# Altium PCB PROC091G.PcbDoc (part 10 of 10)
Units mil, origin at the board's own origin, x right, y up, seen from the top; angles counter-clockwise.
Board outline 4538.11 x 994.94 mil, 8 copper layers (Top Layer, GND1, Sig1, PWR1, PWR2, Sig2, GND2, Bottom Layer), stack 59.155 mil thick; 446 components, 329 nets, 5050 pads, 868 vias.
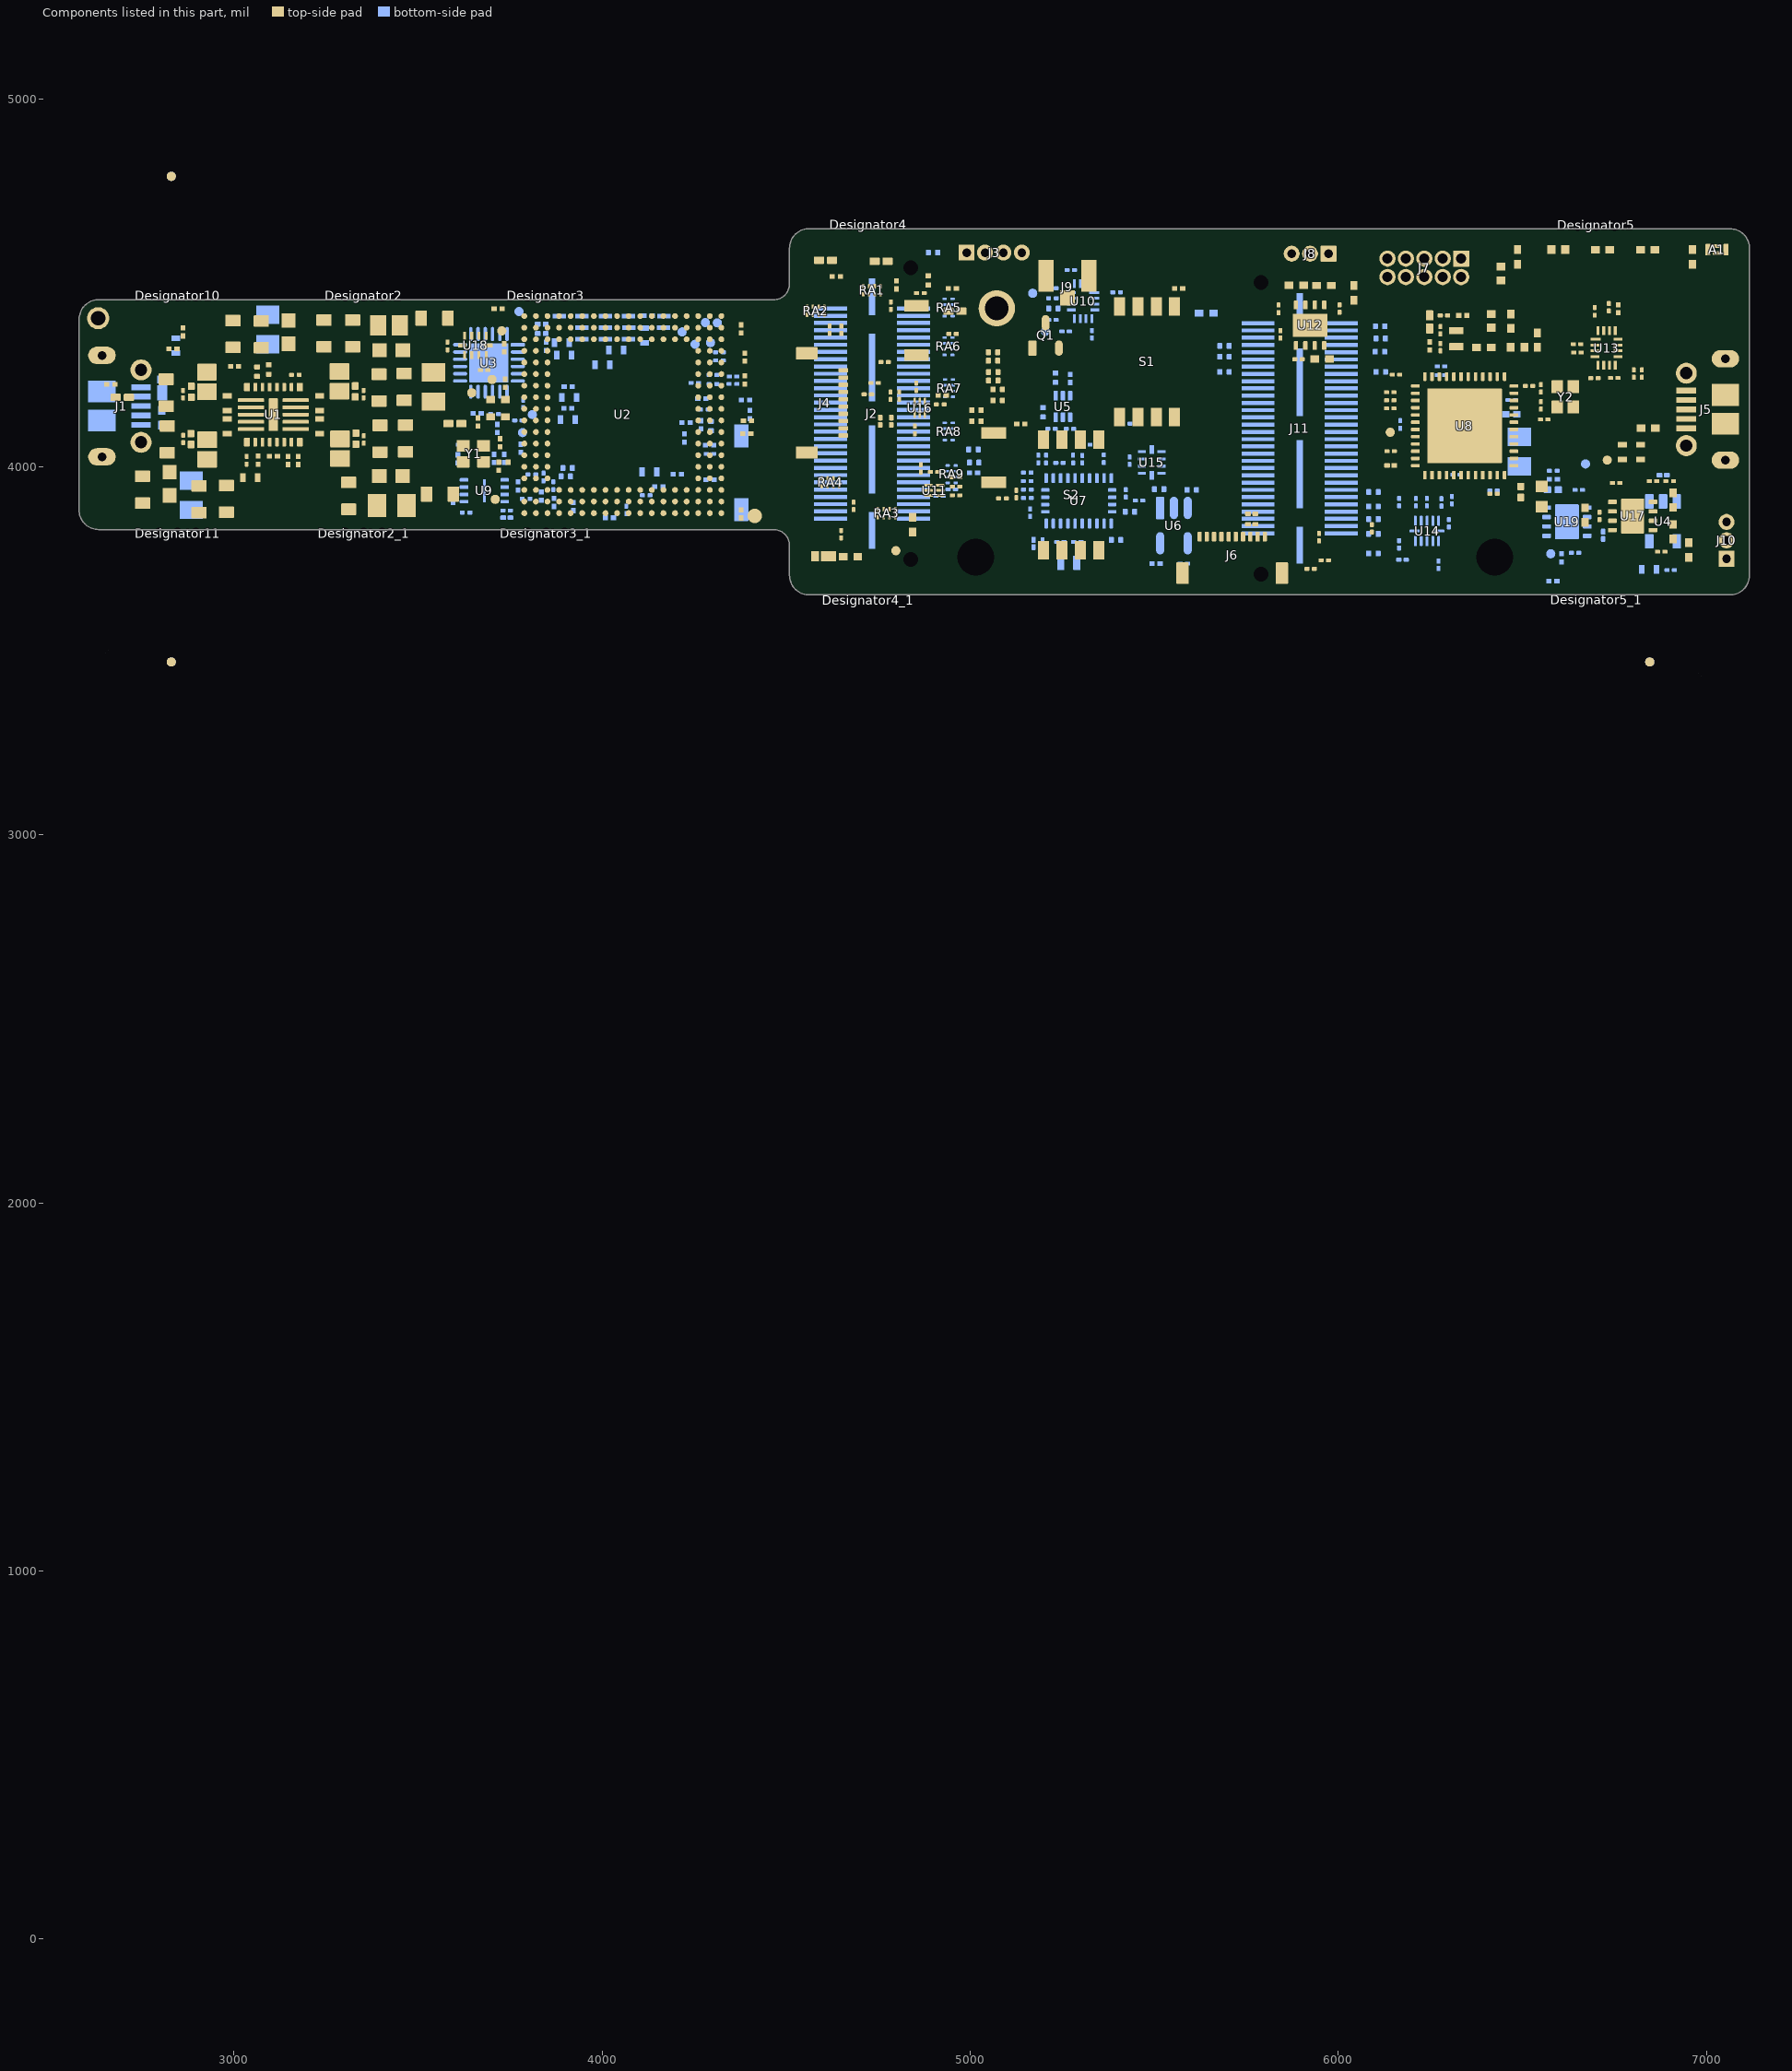
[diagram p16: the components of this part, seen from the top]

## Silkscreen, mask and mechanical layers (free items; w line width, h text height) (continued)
Mechanical 24:
  drawing of 10999 lines, arcs and shapes, not listed
  text "TP33" at 6097.58,6677.7 h30
  text "5V_LED" at 6651.08,6662.7 h30
  text "GND" at 6113.08,6617.7 h30
  text "32" at 8052.58,6517.7 h20
  text "17" at 8422.58,6517.7 h20
  text "U3" at 7956.58,6497.7 h30
  text "D1" at 6081.58,6467.7 h30
  text "33" at 7982.58,6452.7 h20
  text "16" at 8467.58,6452.7 h20
  text "SPARE" at 5513.58,6424.7 h30 r90
  text "DATA_TRAN_PRG" at 5228.58,6398.7 h30 r90
  text "SD_FULL" at 5443.58,6385.7 h30 r90
  text "HDR_ERR" at 5868.58,6380.7 h30 r90
  text "DDR_FULL" at 5588.58,6368.7 h30 r90
  text "LVDS_PATH_ERR" at 5798.58,6363.7 h30 r90
  text "FPGA_ERR" at 5658.58,6358.7 h30 r90
  text "D4" at 7528.58,6350.7 h30 r90
  text "D3" at 7023.58,6346.7 h30 r90
  text "EEPROM_RD_FAIL" at 5998.58,6341.7 h30 r90
  text "D2" at 6548.58,6341.7 h30 r90
  text "SD_DETECT" at 5368.58,6336.7 h30 r90
  text "SW1" at 5689.58,6332.7 h30
  text "6" at 5726.08,6292.7 h20
  text "12BIT_OFF" at 5764.08,6257.7 h30
  text "12BIT_ON" at 5209.58,6232.7 h30
  text "9" at 7141.08,6217.7 h20
  text "9" at 6171.08,6212.7 h20
  text "D6" at 6991.58,6212.7 h30
  text "D8" at 7491.58,6212.7 h30
  text "14BIT_OFF" at 5764.08,6207.7 h30
  text "D7" at 6516.58,6207.7 h30
  text "16" at 7372.58,6202.7 h20
  text "14BIT_ON" at 5209.58,6182.7 h30
  text "16" at 6372.58,6182.7 h20
  text "U1" at 6261.58,6162.7 h30
  text "U2" at 7231.58,6162.7 h30
  text "D5" at 6111.58,6147.7 h30
  text "16BIT_ON" at 5209.58,6132.7 h30
  text "48" at 7952.58,6117.7 h20
  text "3" at 5401.08,6097.7 h20
  text "16BIT_OFF" at 5717.58,6087.7 h30
  text "2" at 8776.08,6074.36 h25
  text "64" at 8412.58,6032.7 h20
  text "49" at 8027.58,6027.7 h20
  text "RADAR_FTDI" at 8900.08,6012.7 h30
  text "Y1" at 8771.58,6002.7 h30
  text "L1" at 5883.58,5997.7 h30
  text "L4" at 7673.58,5980.7 h30 r90
  text "L2" at 6693.58,5972.7 h30 r90
  text "L3" at 6888.58,5970.7 h30 r90
  text "8" at 8763.58,5905.2 h20 r90
  text "USER_SW3" at 5358.58,5867.2 h30 r90
  text "USER_SW2" at 5418.58,5867.2 h30 r90
  text "LVDS_CAPT" at 5743.58,5866.2 h30 r90
  text "USER_SW1" at 5473.58,5862.2 h30 r90
  text "HW_CONFIG" at 5520.25,5858.2 h30 r90
  text "RAW_MODE" at 5578.58,5857.2 h30 r90
  text "3" at 8856.08,5852.7 h20
  text "SD_STORE" at 5678.58,5852.2 h30 r90
  text "1243_MODE" at 5628.58,5843.2 h30 r90
  text "8" at 5296.08,5822.7 h20
  text "D9" at 8779.58,5802.7 h30
  text "LVDS_MODE_SEL" at 5238.58,5747.2 h30 r90
  text "4" at 8480.59,5723.37 h20
  text "5" at 8736.08,5697.7 h20
  text "Y2" at 8273.58,5675.7 h30 r90
  text "U4" at 8581.58,5652.7 h30
  text "2V5" at 7516.08,5622.2 h30 r90
  text "17" at 7892.58,5617.7 h20
  text "SW2" at 5828.58,5603.7 h30 r90
  text "32" at 7562.58,5587.7 h20
  text "U5" at 7176.58,5577.7 h30
  text "J1" at 9096.58,5577.7 h30
  text "5" at 7271.08,5552.7 h20
  text "8" at 7106.08,5547.7 h20
  text "33" at 7482.58,5522.7 h20
  text "16" at 7992.58,5507.7 h20
  text "1V35" at 6414.84,5503.2 h30 r90
  text "9" at 5311.08,5482.7 h20
  text "16" at 5752.58,5472.7 h20
  text "VCC_CORE" at 6179.84,5427.2 h30 r90
  text "U7" at 6421.58,5317.7 h30
  text "8" at 6541.08,5302.7 h20
  text "DATA_MODE" at 5673.58,5183.2 h30 r90
  text "SW_CONFIG" at 5618.58,5178.2 h30 r90
  text "48" at 7487.58,5157.7 h20
  text "ETH_STREAM" at 5773.58,5152.2 h30 r90
  text "AR1642_MODE" at 5723.58,5132.2 h30 r90
  text "DMM_PLAYBACK" at 5823.58,5111.2 h30 r90
  text "4" at 6291.08,5111.03 h20
  text "3" at 5316.08,5087.7 h20
  text "1V1" at 7156.08,5082.2 h30 r90
  text "5" at 6536.08,5072.7 h20
  text "49" at 7587.58,5062.68 h20
  text "64" at 7907.58,5062.68 h20
  text "U6" at 7736.58,5052.7 h30
  text "U8" at 6536.58,4977.7 h30
  text "3" at 6486.08,4937.7 h20
  text "6" at 6676.08,4837.7 h20
  text "4" at 6491.08,4827.7 h20
  text "RADAR_5V_IN" at 5223.58,4770.2 h30 r90
  text "DC_JACK_5V_IN" at 5868.58,4762.2 h30 r90
  text "SW3" at 5449.58,4742.7 h30
  text "U10" at 7609.58,4727.7 h30
  text "U11" at 8089.58,4727.7 h30
  text "FPGA_PROGRAMN_LED" at 5192.08,4652.7 h30
  text "6" at 6406.08,4582.7 h20
  text "J3" at 5826.58,4532.7 h30
  text "U9" at 6268.58,4480.7 h30 r90
  text "FPGA_INITN" at 5245.08,4442.7 h30
  text "3" at 6261.08,4442.7 h20
  text "4" at 6441.08,4427.7 h20
  text "FPGA_RST" at 5253.08,4392.7 h30
  text "2" at 5726.08,4382.7 h20
  text "U12" at 7268.58,4263.7 h30 r90
  text "Q1" at 8551.58,4257.7 h30
  text "FPGA_DONE_LED" at 8753.58,4237.2 h30 r90
  text "FPGA_JTAG" at 8919.08,4187.7 h30
  text "J4" at 9056.58,4122.7 h30
  text "SW4" at 5458.58,4113.7 h30 r90
  text "FPGA_PROGRAMN_SW" at 5218.58,3960.2 h30 r90
  text "5" at 8936.08,3947.7 h20
  text "D10" at 5503.58,3923.7 h30 r90
  text "60_PIN_RADAR_CONN" at 6188.58,3856.2 h30 r90
  text "U13" at 6674.58,3822.7 h30
  text "17" at 8122.58,3822.19 h20
  text "9" at 7507.34,3812.7 h20
  text "D11" at 8839.58,3812.7 h30
  text "3" at 6751.08,3792.7 h20
  text "4" at 6671.08,3787.7 h20
  text "16" at 7108.84,3787.7 h20
  text "59" at 6042.58,3777.7 h20
  text "32" at 7782.58,3777.7 h20
  text "60" at 5732.58,3767.7 h20
  text "U15" at 7699.58,3732.7 h30
  text "33" at 7687.58,3687.7 h20
  text "TP32" at 5527.58,3682.7 h30
  text "SW5" at 5424.58,3672.7 h30
  text "FPGA_CFG0" at 6318.58,3656.7 h30 r90
  text "FPGA_CFG1" at 6368.58,3656.7 h30 r90
  text "2" at 5416.08,3612.7 h20
  text "8" at 6151.08,3597.7 h20
  text "GND" at 5648.58,3577.2 h30 r90
  text "D12" at 5478.58,3568.7 h30 r90
  text "CAPTURE_START" at 5238.58,3562.2 h30 r90
  text "U14" at 7108.58,3555.38 h30 r90
  text "FPGA_CFG2" at 6493.58,3466.7 h30 r90
  text "S1" at 6116.58,3437.7 h30
  text "2" at 5453.08,3422.7 h20
  text "FPGA_RST_SW" at 5696.08,3417.7 h30
  text "D13" at 5569.58,3412.7 h30
  text "D14" at 6034.58,3397.7 h30
  text "48" at 7687.58,3382.7 h20
  text "2" at 5986.08,3377.7 h20
  text "2" at 8556.08,3360.2 h25
  text "8" at 7542.34,3347.7 h20
  text "49" at 7782.58,3307.7 h20
  text "64" at 8157.58,3302.7 h20
  text "Y3" at 8541.58,3302.7 h30
  text "4" at 6441.08,3287.7 h20
  text "3" at 5981.08,3222.7 h20
  text "SPARE_GPIO" at 5228.58,3219.2 h30 r90
  text "SW6" at 5341.58,3212.7 h30
  text "SW7" at 5819.58,3202.7 h30

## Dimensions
2632.58,3367.85 to 2632.58,4930.46 on M2 Board Dimensions
2632.58,3367.85 to 2632.58,4540.76 on M2 Board Dimensions
2632.58,4448.76 to 2632.58,3367.85 on M2 Board Dimensions
2632.27,3834.46 to 2632.58,3367.85 on M2 Board Dimensions
2635,3741.94 to 2632.58,3367.85 on M2 Board Dimensions
2632.58,4448.76 to 2632.27,3834.46 on M2 Board Dimensions
7064.03,3415.8 to 7160.53,3319.29 on M2 Board Dimensions
7112.34,4593.47 to 4514.15,4593.74 on M2 Board Dimensions
2584.58,4448.76 to 7112.34,4593.47 on M2 Board Dimensions
7064.34,4641.38 to 7064.08,3656.83 on M2 Board Dimensions
4466.36,3957.89 to 3922,3330 on M2 Board Dimensions
4489.12,3932.89 to 4466.36,4007.54 on M2 Board Dimensions
4514.12,3982.54 to 4441.36,3957.89 on M2 Board Dimensions
4510.32,3943.73 to 5338.56,3037.37 on M10 Fab Notes
4506.81,4113.64 to 5338.56,3037.37 on M10 Fab Notes
4477.75,4291.3 to 5338.56,3037.37 on M10 Fab Notes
